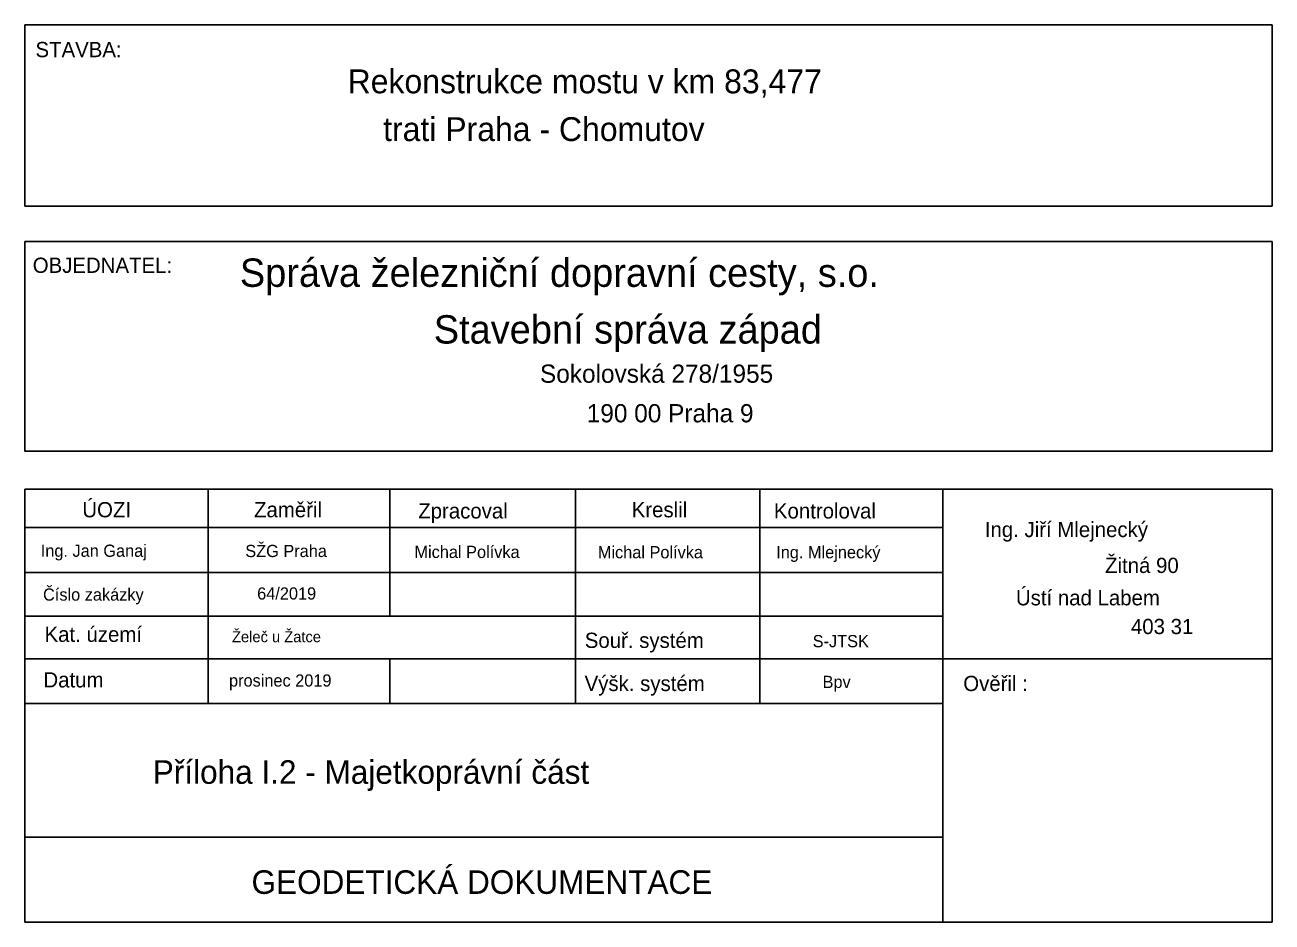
# Model space of a CAD drawing. Extents: x -879530 to -879371, y -1019242 to -1019127.
import ezdxf

# ---------------------------------------------------------------- set-up
doc = ezdxf.new("R2010")
doc.units = 0
doc.layers.add('LEGENDA', color=7, linetype='Continuous')
doc.layers.add('tabulka', color=7, linetype='Continuous')

msp = doc.modelspace()

# ---------------------------------------------------------------- linework, layer by layer
at = {"layer": 'tabulka'}
for p, q in [((-879530.09, -1019186.45), (-879371.44, -1019186.45)), ((-879506.8, -1019186.45), (-879506.8, -1019213.77)), ((-879483.66, -1019186.45), (-879483.66, -1019202.65)), ((-879460.06, -1019186.45), (-879460.06, -1019213.77)), ((-879436.61, -1019186.45), (-879436.61, -1019213.77)), ((-879413.31, -1019241.58), (-879413.31, -1019186.45)), ((-879530.09, -1019191.36), (-879413.31, -1019191.36)), ((-879530.09, -1019197.07), (-879413.31, -1019197.07)), ((-879530.09, -1019202.65), (-879413.31, -1019202.65)), ((-879530.09, -1019208.07), (-879371.44, -1019208.07)), ((-879483.66, -1019208.07), (-879483.66, -1019213.77)), ((-879530.09, -1019213.77), (-879413.31, -1019213.77)), ((-879530.09, -1019230.76), (-879413.31, -1019230.76))]:
    msp.add_line(p, q, dxfattribs=at)
for points in [[(-879530.09, -1019127.36), (-879371.44, -1019127.36), (-879371.44, -1019150.43), (-879530.09, -1019150.43)], [(-879530.09, -1019154.95), (-879371.44, -1019154.95), (-879371.44, -1019181.64), (-879530.09, -1019181.64)]]:
    msp.add_lwpolyline(points, close=True, dxfattribs=at)
msp.add_lwpolyline([(-879371.44, -1019186.45), (-879371.44, -1019241.58), (-879530.09, -1019241.58), (-879530.09, -1019186.45)], dxfattribs=at)

# ---------------------------------------------------------------- texts
at = {"layer": 'LEGENDA'}
for s, p in [('Rekonstrukce mostu v km 83,477 ', (-879489.04, -1019136.07)), ('    trati Praha - Chomutov', (-879489.04, -1019142.15))]:
    msp.add_text(s, height=3.04, dxfattribs=at).set_placement(p)
at = {"layer": 'tabulka'}
for s, height, p in [('STAVBA:', 1.94, (-879528.75, -1019131.47)), ('OBJEDNATEL:', 1.94, (-879529.1, -1019158.93)), ('Správa železniční dopravní cesty, s.o.', 3.61, (-879502.75, -1019160.71)), ('Stavební správa západ', 3.61, (-879478.08, -1019167.93)), ('Sokolovská 278/1955', 2.32, (-879464.57, -1019172.92)), ('190 00 Praha 9', 2.32, (-879458.62, -1019177.96)), ('ÚOZI', 1.94, (-879522.79, -1019190.05)), ('Zaměřil', 1.94, (-879500.95, -1019190.05)), ('Zpracoval', 1.94, (-879480.06, -1019190.2)), ('Kreslil', 1.94, (-879452.9, -1019190.05)), ('Kontroloval', 1.94, (-879434.81, -1019190.2)), ('Ing. Jiří Mlejnecký', 1.94, (-879407.98, -1019192.57)), ('Ing. Jan Ganaj', 1.552, (-879528.08, -1019195.08)), ('SŽG Praha', 1.552, (-879502.06, -1019195.11)), ('Michal Polívka', 1.552, (-879480.54, -1019195.23)), ('Michal Polívka', 1.552, (-879457.21, -1019195.27)), ('Ing. Mlejnecký', 1.552, (-879434.52, -1019195.27)), ('Žitná 90', 1.94, (-879392.68, -1019197.14)), ('Číslo zakázky', 1.552, (-879527.79, -1019200.66)), ('64/2019', 1.552, (-879500.55, -1019200.52)), ('Ústí nad Labem', 1.94, (-879404.02, -1019201.26)), ('403 31', 1.94, (-879389.39, -1019204.92)), ('Kat. území', 1.94, (-879527.6, -1019205.91)), ('Želeč u Žatce', 1.3968, (-879503.75, -1019205.95)), ('Souř. systém', 1.94, (-879458.87, -1019206.68)), ('S-JTSK', 1.552, (-879429.88, -1019206.59)), ('Datum', 1.94, (-879527.74, -1019211.71)), ('prosinec 2019', 1.552, (-879504.13, -1019211.6)), ('Výšk. systém', 1.94, (-879458.89, -1019212.17)), ('Bpv', 1.552, (-879428.62, -1019211.78)), ('Ověřil :', 1.94, (-879410.72, -1019212.17)), ('Příloha I.2 - Majetkoprávní část', 3, (-879513.83, -1019223.98)), ('GEODETICKÁ DOKUMENTACE ', 3, (-879501.27, -1019237.99))]:
    msp.add_text(s, height=height, dxfattribs=at).set_placement(p)

doc.saveas('drawing.dxf')
